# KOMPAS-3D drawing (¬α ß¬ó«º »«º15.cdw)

Referenced files: кр сквоз-1103.cdw
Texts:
  Крышка сквозная
  Noncommercial version
  1. Неуказанный формовочный уклон 5... 7 .
  2. Неуказанные литейные радиусы R = 2 мм max.
  Ra3.2
  Ra6.3
  Ra12.5
  СЧ15  ГОСТ 1412-85
  ДГТУ
Dimensions and other numbers on the sheet: 108; 88; 36; 15; 8; 20; 14; 50; 60; 68; 0,016; 4; 6; 4 отв.; 2:1; 1; 0.42; 0; 2; 3; 5; 7; 9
